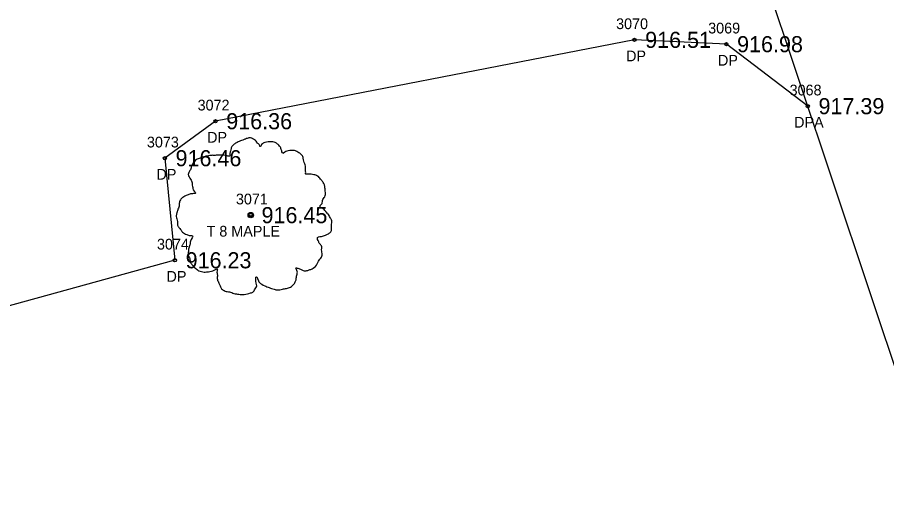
# Model space of a CAD drawing. Extents: x 1528109 to 1531398, y 1157799 to 1162548.
# Drawn here: x 1529754.4 to 1529835.3, y 1159675.3 to 1159719.3 of the extents above; entities that cross this region are included whole.
import ezdxf

# ---------------------------------------------------------------- set-up
doc = ezdxf.new("R2010")
doc.units = 0
for name, color, linetype in [('RD_EX_Driveway', 7, 'Continuous'), ('RD_EX_Driveway_txCode', 7, 'Continuous'), ('RD_EX_Road', 7, 'Continuous'), ('RD_EX_TX_Driveway_ELEV', 7, 'Continuous'), ('RD_EX_TX_VEG_ELEV', 7, 'Continuous'), ('RD_EX_VEG', 7, 'Continuous'), ('RD_EX_VEG_txCode', 7, 'Continuous'), ('RD_SMD_Locator', 7, 'Continuous')]:
    doc.layers.add(name, color=color, linetype=linetype)

msp = doc.modelspace()

# ---------------------------------------------------------------- linework, layer by layer
at = {"layer": 'RD_EX_Driveway'}
msp.add_lwpolyline([(1529828.003, 1159711.071), (1529820.417, 1159716.844), (1529811.854, 1159717.248), (1529772.822, 1159709.667), (1529768.099, 1159706.22), (1529769.037, 1159696.71), (1529743.09, 1159689.583)], dxfattribs=at)
at = {"layer": 'RD_EX_Road'}
msp.add_lwpolyline([(1530332.276, 1159136.668), (1530288.961, 1159147.056), (1530245.679, 1159158.002), (1530197.525, 1159172.184), (1530159.104, 1159186.574), (1530108.597, 1159214.893), (1530072.674, 1159242.37), (1530037.118, 1159276.962), (1530005.208, 1159311.503), (1529961.591, 1159366.877), (1529941.786, 1159398.289), (1529924.064, 1159434.111), (1529903.768, 1159484.387), (1529891.443, 1159520.805), (1529876.794, 1159564.704), (1529862.9, 1159606.82), (1529836.939, 1159684.287), (1529820.656, 1159733.094), (1529800.023, 1159794.401), (1529769.543, 1159884.464)], dxfattribs=at)
at = {"layer": 'RD_EX_VEG'}
for centre, radius in [((1529776.11, 1159700.916), 0.25), ((1529776.097, 1159700.897), 0.0001)]:
    msp.add_circle(centre, radius, dxfattribs=at)
for points in [[(1529776.242, 1159708.083), (1529775.942, 1159708.108), (1529775.617, 1159708.008), (1529775.367, 1159707.908), (1529775.142, 1159707.833), (1529774.918, 1159707.733), (1529774.618, 1159707.559), (1529774.393, 1159707.359), (1529774.268, 1159707.109), (1529774.218, 1159706.884), (1529774.168, 1159706.609), (1529774.168, 1159706.434), (1529774.043, 1159706.409), (1529773.893, 1159706.434), (1529773.643, 1159706.509), (1529773.393, 1159706.509), (1529773.143, 1159706.509), (1529772.793, 1159706.484), (1529772.444, 1159706.484), (1529772.169, 1159706.434), (1529771.844, 1159706.384), (1529771.469, 1159706.259), (1529771.119, 1159706.134), (1529770.819, 1159705.884), (1529770.569, 1159705.41), (1529770.444, 1159705.06), (1529770.295, 1159704.81), (1529770.444, 1159704.36), (1529770.619, 1159704.01), (1529770.644, 1159703.81), (1529770.719, 1159703.385), (1529770.819, 1159703.161), (1529770.944, 1159702.961), (1529770.869, 1159702.936), (1529770.494, 1159702.886), (1529770.195, 1159702.786), (1529769.77, 1159702.561), (1529769.545, 1159702.336), (1529769.445, 1159702.011), (1529769.42, 1159701.661), (1529769.32, 1159701.461), (1529769.245, 1159701.186), (1529769.22, 1159701.111), (1529769.17, 1159700.787), (1529769.27, 1159700.337), (1529769.295, 1159699.987), (1529769.42, 1159699.762), (1529769.57, 1159699.587), (1529769.745, 1159699.337), (1529770.145, 1159699.112), (1529770.469, 1159699.012), (1529770.669, 1159698.987), (1529770.494, 1159698.488), (1529770.444, 1159698.138), (1529770.32, 1159697.738), (1529770.32, 1159697.663), (1529770.27, 1159697.188), (1529770.419, 1159696.863), (1529770.494, 1159696.488), (1529770.669, 1159696.264), (1529770.944, 1159695.964), (1529771.269, 1159695.739), (1529771.769, 1159695.614), (1529772.169, 1159695.639), (1529772.744, 1159695.814), (1529772.993, 1159695.889), (1529772.968, 1159695.714), (1529772.993, 1159695.339), (1529772.993, 1159694.914), (1529773.143, 1159694.589), (1529773.243, 1159694.314), (1529773.393, 1159694.064), (1529773.718, 1159693.84), (1529774.118, 1159693.765), (1529774.543, 1159693.615), (1529774.993, 1159693.54), (1529775.492, 1159693.515), (1529776.092, 1159693.665), (1529776.367, 1159693.79), (1529776.467, 1159693.965), (1529776.667, 1159694.339), (1529776.617, 1159694.564), (1529776.642, 1159695.164), (1529776.742, 1159694.989), (1529776.917, 1159694.639), (1529777.416, 1159694.339), (1529777.816, 1159694.164), (1529778.291, 1159694.014), (1529778.591, 1159693.94), (1529779.066, 1159694.014), (1529779.441, 1159694.089), (1529779.815, 1159694.214), (1529780.115, 1159694.489), (1529780.29, 1159694.764), (1529780.34, 1159695.039), (1529780.415, 1159695.414), (1529780.465, 1159695.589)], [(1529780.465, 1159695.589), (1529780.39, 1159695.764), (1529780.34, 1159696.014), (1529780.415, 1159695.989), (1529780.59, 1159695.939), (1529780.865, 1159695.814), (1529781.09, 1159695.739), (1529781.415, 1159695.764), (1529781.69, 1159695.864), (1529782.139, 1159696.139), (1529782.414, 1159696.613), (1529782.689, 1159697.013), (1529782.764, 1159697.338), (1529782.714, 1159697.563), (1529782.689, 1159698.063), (1529782.489, 1159698.313), (1529782.439, 1159698.438), (1529782.339, 1159698.837), (1529782.414, 1159698.887), (1529782.689, 1159698.937), (1529783.064, 1159699.062), (1529783.339, 1159699.187), (1529783.564, 1159699.362), (1529783.639, 1159699.587), (1529783.614, 1159699.987), (1529783.664, 1159700.387), (1529783.589, 1159700.537), (1529783.489, 1159700.687), (1529783.414, 1159700.887), (1529783.264, 1159701.036), (1529783.164, 1159701.186), (1529783.064, 1159701.286), (1529782.939, 1159701.436), (1529782.764, 1159701.561), (1529782.614, 1159701.611), (1529782.564, 1159701.761), (1529782.714, 1159701.961), (1529782.764, 1159702.061), (1529782.789, 1159702.286), (1529783.014, 1159702.636), (1529783.064, 1159703.036), (1529783.014, 1159703.46), (1529782.964, 1159703.735), (1529782.814, 1159704.01), (1529782.614, 1159704.26), (1529782.489, 1159704.435), (1529782.314, 1159704.56), (1529781.989, 1159704.685), (1529781.74, 1159704.735), (1529781.39, 1159704.735), (1529781.19, 1159704.785), (1529781.215, 1159704.835), (1529781.215, 1159704.985), (1529781.215, 1159705.26), (1529781.14, 1159705.709), (1529780.99, 1159706.209), (1529780.99, 1159706.234), (1529780.89, 1159706.484), (1529780.665, 1159706.684), (1529780.49, 1159706.784), (1529780.29, 1159706.909), (1529780.04, 1159706.934), (1529779.74, 1159706.934), (1529779.466, 1159706.884), (1529779.266, 1159706.784), (1529779.091, 1159706.659), (1529779.016, 1159706.809), (1529778.916, 1159707.109), (1529778.866, 1159707.259), (1529778.716, 1159707.434), (1529778.491, 1159707.634), (1529778.041, 1159707.758), (1529777.416, 1159707.684), (1529777.117, 1159707.484), (1529776.967, 1159707.309), (1529776.917, 1159707.434), (1529776.717, 1159707.634), (1529776.617, 1159707.808), (1529776.442, 1159707.933), (1529776.292, 1159708.033), (1529776.192, 1159708.083)]]:
    msp.add_spline(points, degree=3, dxfattribs=at)
at = {"layer": 'RD_SMD_Locator'}
for centre in [(1529811.854, 1159717.248), (1529820.417, 1159716.844), (1529828.003, 1159711.071), (1529772.822, 1159709.667), (1529768.099, 1159706.22), (1529776.11, 1159700.916), (1529769.037, 1159696.71)]:
    msp.add_circle(centre, 0.15, dxfattribs=at)

# ---------------------------------------------------------------- texts
at = {"layer": 'RD_EX_Driveway_txCode'}
for s, p in [('3070', (1529810.146, 1159718.248)), ('3069', (1529818.724, 1159717.844)), ('DP', (1529811.075, 1159715.248)), ('DP', (1529819.637, 1159714.844)), ('3068', (1529826.31, 1159712.071)), ('3072', (1529771.153, 1159710.667)), ('DPA', (1529826.736, 1159709.071)), ('3073', (1529766.43, 1159707.22)), ('DP', (1529772.042, 1159707.667)), ('DP', (1529767.32, 1159704.22)), ('3074', (1529767.367, 1159697.71)), ('DP', (1529768.257, 1159694.71))]:
    msp.add_text(s, height=1, dxfattribs=at).set_placement(p)
at = {"layer": 'RD_EX_TX_Driveway_ELEV'}
for s, p in [('916.51', (1529812.854, 1159716.498)), ('916.98', (1529821.417, 1159716.094)), ('917.39', (1529829.003, 1159710.321)), ('916.36', (1529773.822, 1159708.917)), ('916.46', (1529769.099, 1159705.47)), ('916.23', (1529770.037, 1159695.96))]:
    msp.add_text(s, height=1.5, dxfattribs=at).set_placement(p)
at = {"layer": 'RD_EX_TX_VEG_ELEV'}
msp.add_text('916.45', height=1.5, dxfattribs=at).set_placement((1529777.11, 1159700.166))
at = {"layer": 'RD_EX_VEG_txCode'}
for s, p in [('3071', (1529774.724, 1159701.916)), ('T 8 MAPLE', (1529771.988, 1159698.916))]:
    msp.add_text(s, height=1, dxfattribs=at).set_placement(p)

doc.saveas('drawing.dxf')
